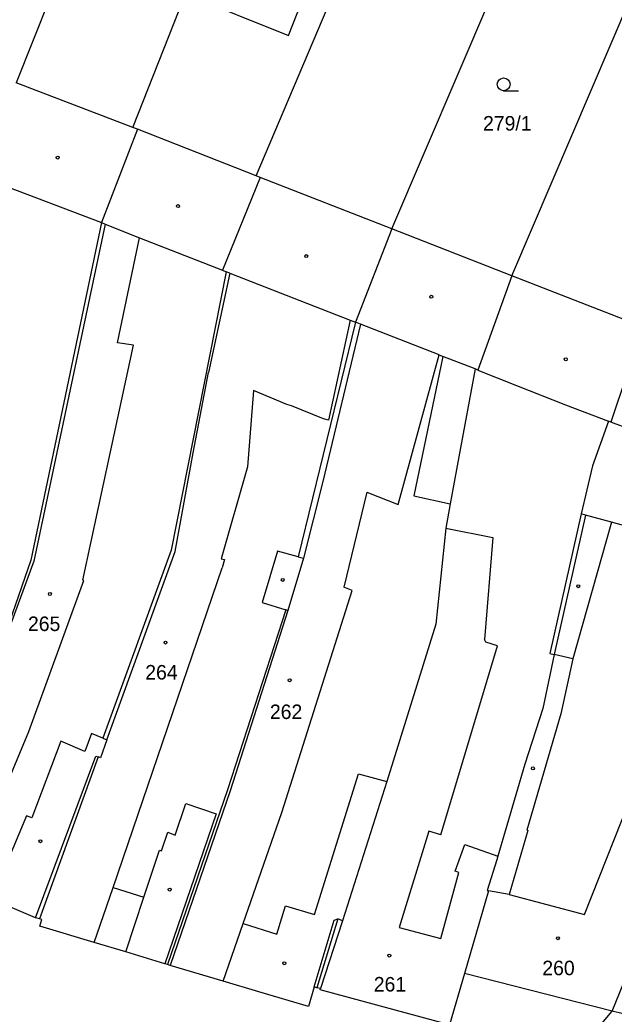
# Model space of a CAD drawing. Extents: x -757266 to -753360, y -1162585 to -1157740.
# Drawn here: x -754953.1 to -754883.4, y -1161387.6 to -1161271.1 of the extents above; entities that cross this region are included whole.
import ezdxf

# ---------------------------------------------------------------- set-up
doc = ezdxf.new("R2010")
doc.units = 0
for name, color, linetype in [('Hranice parcel', 7, 'Continuous'), ('Parcelní čísla', 7, 'Continuous'), ('Vnitřní kresba', 7, 'Continuous'), ('Značky budov', 7, 'Continuous'), ('Značky kultur', 7, 'Continuous')]:
    doc.layers.add(name, color=color, linetype=linetype)

msp = doc.modelspace()

# ---------------------------------------------------------------- linework, layer by layer
at = {"layer": 'Hranice parcel'}
for p, q in [((-754920.84, -1161196.79), (-754953.52, -1161278.5)), ((-754925.39, -1161289.43), (-754895.64, -1161219.25)), ((-754909.49, -1161295.63), (-754894.24, -1161259.96)), ((-754895.4, -1161301.13), (-754880.19, -1161265.48)), ((-754939.86, -1161283.75), (-754933.69, -1161268.1)), ((-754939.86, -1161283.75), (-754953.52, -1161278.5)), ((-754939.3, -1161283.96), (-754939.86, -1161283.75)), ((-754925.39, -1161289.43), (-754939.3, -1161283.96)), ((-754924.92, -1161289.62), (-754925.39, -1161289.43)), ((-754909.49, -1161295.63), (-754924.92, -1161289.62)), ((-754895.4, -1161301.13), (-754909.49, -1161295.63)), ((-754880.04, -1161307.13), (-754895.4, -1161301.13)), ((-754883.65, -1161387.31), (-754900.95, -1161382.88)), ((-754882.35, -1161387.63), (-754883.65, -1161387.31))]:
    msp.add_line(p, q, dxfattribs=at)
for points in [[(-754933.69, -1161268.1), (-754921.58, -1161272.99), (-754917.53, -1161262.63), (-754929.67, -1161257.75)], [(-754939.3, -1161283.96), (-754943.51, -1161294.9), (-754951.79, -1161334.47), (-754955.48, -1161344.96)], [(-754924.92, -1161289.62), (-754929.34, -1161300.49), (-754928.9, -1161300.66), (-754935.35, -1161333.28), (-754943.35, -1161355.33), (-754942.89, -1161355.52), (-754943.64, -1161357.62), (-754943.92, -1161357.51), (-754950.78, -1161376.48)], [(-754909.49, -1161295.63), (-754913.75, -1161306.57), (-754920.48, -1161334.05), (-754919.84, -1161334.22), (-754921.67, -1161340.36), (-754921.9, -1161340.29), (-754928.75, -1161361.38), (-754935.78, -1161381.83)], [(-754895.4, -1161301.13), (-754899.4, -1161312.18), (-754899.73, -1161312.04), (-754901.62, -1161322.33), (-754902.64, -1161327.87), (-754903.16, -1161330.69), (-754904.31, -1161341.94), (-754910.08, -1161360.38), (-754915.27, -1161376.7), (-754915.8, -1161376.49), (-754918.28, -1161384.58)], [(-754880.04, -1161307.13), (-754883.81, -1161318.28), (-754884.09, -1161318.17), (-754885.96, -1161323.39), (-754887.3, -1161329.04), (-754890.95, -1161345.41), (-754890.47, -1161345.5), (-754891.8, -1161351.82), (-754893.88, -1161358.36), (-754897.04, -1161369.14), (-754897.17, -1161369.59), (-754898.3, -1161373.16), (-754898.17, -1161373.19), (-754900.95, -1161382.88)], [(-754883.65, -1161387.31), (-754875.08, -1161366.29), (-754860, -1161328.06), (-754859.78, -1161327.43), (-754855.75, -1161316.78)], [(-754950.78, -1161376.48), (-754951.24, -1161376.36), (-754956.43, -1161374.18), (-754959.67, -1161372.82), (-754965.5, -1161370.38), (-754964.62, -1161368.27), (-754964.88, -1161368.16)], [(-754935.78, -1161381.83), (-754936.1, -1161381.75), (-754940.68, -1161380.37), (-754944.38, -1161379.26), (-754950.74, -1161377.34), (-754950.5, -1161376.55), (-754950.78, -1161376.48)], [(-754918.28, -1161384.58), (-754918.6, -1161384.45), (-754919.27, -1161386.74), (-754925.07, -1161385.02), (-754929.24, -1161383.79), (-754935.48, -1161381.95), (-754935.78, -1161381.83)], [(-754900.95, -1161382.88), (-754902.73, -1161388.92), (-754917.87, -1161384.79), (-754917.83, -1161384.65), (-754918.28, -1161384.58)], [(-754907.76, -1161416.74), (-754906.11, -1161414.09), (-754883.65, -1161387.31)]]:
    msp.add_lwpolyline(points, dxfattribs=at)
at = {"layer": 'Vnitřní kresba'}
for p, q in [((-754957.86, -1161289.45), (-754943.51, -1161294.9)), ((-754943.1, -1161295.1), (-754951.45, -1161334.57)), ((-754943.51, -1161294.9), (-754943.1, -1161295.1)), ((-754943.1, -1161295.1), (-754939.07, -1161296.68)), ((-754941.63, -1161308.97), (-754939.07, -1161296.68)), ((-754939.07, -1161296.68), (-754929.34, -1161300.49)), ((-754928.47, -1161300.83), (-754930.99, -1161312.48)), ((-754928.47, -1161300.83), (-754928.9, -1161300.66)), ((-754928.47, -1161300.83), (-754914.37, -1161306.33)), ((-754913.15, -1161306.8), (-754917.59, -1161325.25)), ((-754914.37, -1161306.33), (-754916.9, -1161318.05)), ((-754914.37, -1161306.33), (-754913.75, -1161306.57)), ((-754913.15, -1161306.8), (-754913.75, -1161306.57)), ((-754903.95, -1161310.4), (-754913.15, -1161306.8)), ((-754939.77, -1161309.27), (-754941.63, -1161308.97)), ((-754944.74, -1161332.28), (-754939.77, -1161309.27)), ((-754908.75, -1161327.92), (-754903.95, -1161310.4)), ((-754903.49, -1161310.57), (-754906.91, -1161326.92)), ((-754903.95, -1161310.4), (-754903.49, -1161310.57)), ((-754899.73, -1161312.04), (-754903.49, -1161310.57)), ((-754932.78, -1161321.88), (-754930.99, -1161312.48)), ((-754899.4, -1161312.18), (-754894.88, -1161313.99)), ((-754925.71, -1161314.56), (-754926.4, -1161323.53)), ((-754921.8, -1161316.22), (-754925.71, -1161314.56)), ((-754894.88, -1161313.99), (-754889.12, -1161316.24)), ((-754921.23, -1161316.37), (-754921.8, -1161316.22)), ((-754917.49, -1161317.91), (-754921.23, -1161316.37)), ((-754889.12, -1161316.24), (-754884.09, -1161318.17)), ((-754916.9, -1161318.05), (-754917.49, -1161317.91)), ((-754874.18, -1161321.95), (-754883.81, -1161318.28)), ((-754934.87, -1161333.44), (-754932.78, -1161321.88)), ((-754926.4, -1161323.53), (-754929.48, -1161334.28)), ((-754917.59, -1161325.25), (-754919.84, -1161334.22)), ((-754886.91, -1161375.96), (-754866.82, -1161325.34)), ((-754912.41, -1161326.49), (-754915.12, -1161337.62)), ((-754912.41, -1161326.49), (-754908.75, -1161327.92)), ((-754906.91, -1161326.92), (-754902.64, -1161327.87)), ((-754886.76, -1161329.19), (-754890.47, -1161345.5)), ((-754883.75, -1161330.01), (-754888.28, -1161346.01)), ((-754886.76, -1161329.19), (-754887.3, -1161329.04)), ((-754883.75, -1161330.01), (-754886.76, -1161329.19)), ((-754877.33, -1161331.75), (-754883.75, -1161330.01)), ((-754903.16, -1161330.69), (-754897.64, -1161331.81)), ((-754945.7, -1161336.8), (-754944.74, -1161332.28)), ((-754897.64, -1161331.81), (-754898.6, -1161343.75)), ((-754942.89, -1161355.52), (-754934.87, -1161333.44)), ((-754922.87, -1161333.4), (-754924.7, -1161339.43)), ((-754920.48, -1161334.05), (-754922.87, -1161333.4)), ((-754951.45, -1161334.57), (-754957.79, -1161351.73)), ((-754929.48, -1161334.28), (-754929.12, -1161334.39)), ((-754929.12, -1161334.39), (-754929.36, -1161335.35)), ((-754942.17, -1161372.8), (-754929.36, -1161335.35)), ((-754952.04, -1161354.52), (-754945.6, -1161336.84)), ((-754945.6, -1161336.84), (-754945.7, -1161336.8)), ((-754922.36, -1161364.01), (-754914.12, -1161338.01)), ((-754914.12, -1161338.01), (-754915.12, -1161337.62)), ((-754924.7, -1161339.43), (-754921.9, -1161340.29)), ((-754921.67, -1161340.36), (-754928.44, -1161361.49)), ((-754898.45, -1161344.08), (-754898.6, -1161343.75)), ((-754897.1, -1161344.49), (-754898.45, -1161344.08)), ((-754903.75, -1161366.63), (-754897.1, -1161344.49)), ((-754888.28, -1161346.01), (-754890.47, -1161345.5)), ((-754888.28, -1161346.01), (-754889.66, -1161352.48)), ((-754889.66, -1161352.48), (-754893.64, -1161366.08)), ((-754959.67, -1161372.82), (-754952.04, -1161354.52)), ((-754948.28, -1161355.66), (-754951.67, -1161364.63)), ((-754945.49, -1161356.86), (-754948.28, -1161355.66)), ((-754944.68, -1161354.77), (-754945.49, -1161356.86)), ((-754943.35, -1161355.33), (-754944.68, -1161354.77)), ((-754951.24, -1161376.36), (-754944.18, -1161357.41)), ((-754944.18, -1161357.41), (-754943.92, -1161357.51)), ((-754918.56, -1161375.97), (-754913.4, -1161359.48)), ((-754913.4, -1161359.48), (-754910.08, -1161360.38)), ((-754928.44, -1161361.49), (-754935.48, -1161381.95)), ((-754934.9, -1161366.67), (-754933.65, -1161362.97)), ((-754933.65, -1161362.97), (-754930.06, -1161364.18)), ((-754952.32, -1161364.4), (-754956.43, -1161374.18)), ((-754951.67, -1161364.63), (-754952.32, -1161364.4)), ((-754930.06, -1161364.18), (-754936.1, -1161381.75)), ((-754926.92, -1161377.05), (-754922.36, -1161364.01)), ((-754905.14, -1161366.21), (-754908.61, -1161377.51)), ((-754903.75, -1161366.63), (-754905.14, -1161366.21)), ((-754893.53, -1161366.13), (-754895.74, -1161373.62)), ((-754893.64, -1161366.08), (-754893.53, -1161366.13)), ((-754936.49, -1161368.52), (-754935.76, -1161366.33)), ((-754935.76, -1161366.33), (-754934.9, -1161366.67)), ((-754938.54, -1161373.93), (-754936.72, -1161368.44)), ((-754936.72, -1161368.44), (-754936.49, -1161368.52)), ((-754902.05, -1161370.91), (-754900.93, -1161367.77)), ((-754900.93, -1161367.77), (-754897.04, -1161369.14)), ((-754903.75, -1161378.79), (-754901.63, -1161371.06)), ((-754901.63, -1161371.06), (-754902.05, -1161370.91)), ((-754944.38, -1161379.26), (-754942.17, -1161372.8)), ((-754942.17, -1161372.8), (-754938.54, -1161373.93)), ((-754895.74, -1161373.62), (-754898.17, -1161373.19)), ((-754940.68, -1161380.37), (-754938.54, -1161373.93)), ((-754895.74, -1161373.62), (-754886.91, -1161375.96)), ((-754922.97, -1161378.27), (-754921.96, -1161374.96)), ((-754921.96, -1161374.96), (-754918.56, -1161375.97)), ((-754918.6, -1161384.45), (-754916.26, -1161376.65)), ((-754915.27, -1161376.7), (-754917.83, -1161384.65)), ((-754916.26, -1161376.65), (-754915.8, -1161376.49)), ((-754929.24, -1161383.79), (-754926.92, -1161377.05)), ((-754926.92, -1161377.05), (-754922.97, -1161378.27)), ((-754908.61, -1161377.51), (-754903.75, -1161378.79))]:
    msp.add_line(p, q, dxfattribs=at)
at = {"layer": 'Značky budov'}
for centre in [(-754948.6568, -1161287.2692), (-754934.5468, -1161292.9592), (-754919.5168, -1161298.8192), (-754904.8568, -1161303.5892), (-754889.0968, -1161310.9192), (-754922.2668, -1161336.7692), (-754949.5768, -1161338.4192), (-754887.6268, -1161337.5092), (-754936.0168, -1161344.1092), (-754921.4568, -1161348.5292), (-754892.9468, -1161358.8492), (-754950.6768, -1161367.3892), (-754935.5268, -1161373.0592), (-754890.0168, -1161378.7592), (-754909.7768, -1161380.7892), (-754922.0868, -1161381.6892)]:
    msp.add_circle(centre, 0.175, dxfattribs=at)
at = {"layer": 'Značky kultur'}
msp.add_line((-754896.373, -1161279.44), (-754894.623, -1161279.44), dxfattribs=at)
msp.add_circle((-754896.3729, -1161278.6898), 0.75, dxfattribs=at)

# ---------------------------------------------------------------- texts
at = {"layer": 'Parcelní čísla'}
for s, p in [('279/1', (-754898.79, -1161284.11)), ('265', (-754952.14, -1161342.76)), ('264', (-754938.39, -1161348.44)), ('262', (-754923.78, -1161353.07)), ('260', (-754891.84, -1161383.09)), ('261', (-754911.6, -1161385))]:
    msp.add_text(s, height=1.7, dxfattribs=at).set_placement(p)

doc.saveas('drawing.dxf')
